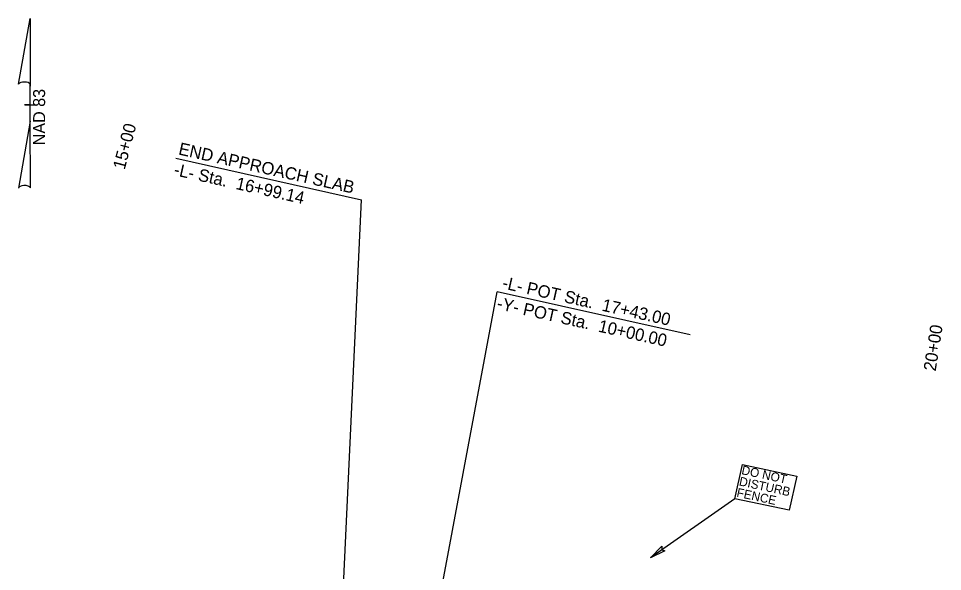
# Model space of a CAD drawing. Extents: x 1784740 to 1786163, y 841056 to 841833.
# Drawn here: x 1785471 to 1785994, y 841520 to 841833 of the extents above; entities that cross this region are included whole.
import ezdxf

# ---------------------------------------------------------------- set-up
doc = ezdxf.new("R2010")
doc.units = 0
for name, color, linetype in [('Prop DSN Text', 7, 'Continuous'), ('Prop Horizontal Alignment Station Label', 7, 'Continuous'), ('Prop Horizontal Alignment Tick Label', 7, 'Continuous'), ('Prop North Arrow NAD83 for Plan Sheets CELL', 7, 'Continuous'), ('Prop Plan Preparation Information Additional Label', 7, 'Continuous'), ('Prop Terminator CELL', 7, 'Continuous')]:
    doc.layers.add(name, color=color, linetype=linetype)

msp = doc.modelspace()

# ---------------------------------------------------------------- linework, layer by layer
at = {"layer": 'Prop DSN Text'}
for p in [(1785560.21, 841754.11), (1785651.4, 841433.33)]:
    msp.add_line(p, (1785665.25, 841730.55), dxfattribs=at)
at = {"layer": 'Prop Horizontal Alignment Station Label'}
for p in [(1785693.82, 841422.21), (1785850.98, 841654.11)]:
    msp.add_line(p, (1785741.97, 841678.56), dxfattribs=at)
at = {"layer": 'Prop North Arrow NAD83 for Plan Sheets CELL'}
for p, q in [((1785471.27, 841795.97), (1785477.82, 841833.05)), ((1785477.86, 841833.05), (1785477.82, 841833.05)), ((1785477.86, 841833.05), (1785477.82, 841833.05)), ((1785477.86, 841833.05), (1785477.87, 841794.81)), ((1785477.88, 841774.97), (1785477.87, 841795.93)), ((1785477.87, 841794.81), (1785477.87, 841795.89)), ((1785474.68, 841784.25), (1785474.64, 841784.25)), ((1785477.52, 841784.25), (1785474.68, 841784.25)), ((1785474.72, 841784.25), (1785481.12, 841784.25)), ((1785477.88, 841774.97), (1785471.22, 841737.17)), ((1785477.94, 841737.33), (1785477.88, 841774.97))]:
    msp.add_line(p, q, dxfattribs=at)
for centre, start_param, end_param in [((1785474.58, 841795.57), 0.216388, 2.908219), ((1785474.61, 841737.04), 0.201328, 3.141593)]:
    msp.add_ellipse(centre, major_axis=(3.38, -0.02), ratio=0.461098, start_param=start_param, end_param=end_param, dxfattribs=at)
at = {"layer": 'Prop Plan Preparation Information Additional Label'}
msp.add_line((1785876.36, 841561.46), (1785828.51, 841528.08), dxfattribs=at)
msp.add_lwpolyline([(1785880.7, 841580.82), (1785911.33, 841574.28), (1785906.99, 841554.92), (1785876.36, 841561.46)], close=True, dxfattribs=at)
at = {"layer": 'Prop Terminator CELL'}
msp.add_lwpolyline([(1785836.78, 841531.96), (1785828.51, 841528.08), (1785835.02, 841534.57), (1785834.99, 841532.6)], close=True, dxfattribs=at)

# ---------------------------------------------------------------- texts
at = {"layer": 'Prop DSN Text'}
for s, p in [('END APPROACH SLAB', (1785561.29, 841756.21)), ('-L- Sta.  16+99.14', (1785558.66, 841744.51))]:
    msp.add_text(s, height=7, rotation=347.3599, dxfattribs=at).set_placement(p)
at = {"layer": 'Prop Horizontal Alignment Station Label'}
for s, p in [('-L- POT Sta.  17+43.00', (1785744.35, 841680.49)), ('-Y- POT Sta.  10+00.00', (1785741.3, 841668.87))]:
    msp.add_text(s, height=7, rotation=347.3599, dxfattribs=at).set_placement(p)
at = {"layer": 'Prop Horizontal Alignment Tick Label'}
for s, rotation, p in [('15+00', 75.315, (1785531.26, 841747.19)), ('20+00', 81.2176, (1785989.85, 841633.3))]:
    msp.add_text(s, height=7, rotation=rotation, dxfattribs=at).set_placement(p)
at = {"layer": 'Prop North Arrow NAD83 for Plan Sheets CELL'}
msp.add_text('NAD 83', height=6.8, rotation=90.0239, dxfattribs=at).set_placement((1785486.3, 841761.37))
at = {"layer": 'Prop Plan Preparation Information Additional Label'}
for s, p in [('DO NOT', (1785879.74, 841575.44)), ('DISTURB', (1785878.36, 841569.08)), ('FENCE', (1785876.98, 841562.73))]:
    msp.add_text(s, height=5, rotation=347.7272, dxfattribs=at).set_placement(p)

doc.saveas('drawing.dxf')
